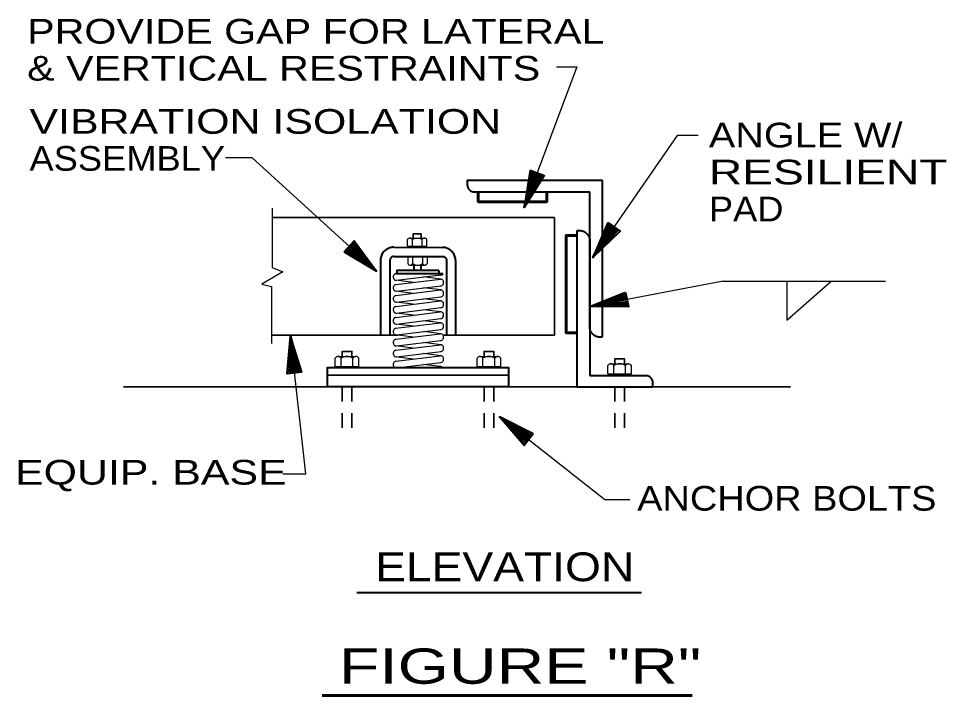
# Model space of a CAD drawing. Extents: x 55 to 190, y 198 to 264.
# Drawn here: x 115.65 to 125.21, y 242.67 to 249.64 of the extents above; entities that cross this region are included whole.
import ezdxf
from ezdxf.enums import TextEntityAlignment as Align

# ---------------------------------------------------------------- set-up
doc = ezdxf.new("R2010")
doc.units = 0
doc.header["$LTSCALE"] = 0.1
doc.linetypes.add('SHORT_DASHED', pattern=[2.7, 1.5, -1.2])
doc.layers.add('2', color=7, linetype='Continuous', lineweight=40)

msp = doc.modelspace()

# ---------------------------------------------------------------- linework, layer by layer
at = {"layer": '2'}
for p, q in [((120.856, 247.6946), (120.9367, 248.0727)), ((120.856, 247.6946), (120.9568, 248.0658)), ((120.856, 247.6946), (120.9727, 248.0592)), ((120.9894, 248.0534), (120.856, 247.6946)), ((120.856, 247.6946), (121.0073, 248.0462)), ((120.856, 247.6946), (121.0423, 248.0333)), ((121.6633, 246.3629), (121.6633, 247.9724)), ((121.532, 246.4542), (121.532, 247.857)), ((121.5632, 247.1826), (121.7344, 247.5292)), ((121.5632, 247.1826), (121.7524, 247.5176)), ((121.4008, 247.4567), (121.4008, 245.8473)), ((121.4474, 247.4567), (121.4008, 247.4567)), ((121.5632, 247.1826), (121.7659, 247.5073)), ((121.7807, 247.4975), (121.5632, 247.1826)), ((121.5632, 247.1826), (121.7963, 247.4864)), ((121.5632, 247.1826), (121.827, 247.4649)), ((119.3362, 247.0397), (119.0912, 247.3387)), ((121.532, 247.3654), (121.532, 245.9626)), ((119.3362, 247.0397), (119.0153, 247.2554)), ((119.3362, 247.0397), (119.0293, 247.2715)), ((119.3362, 247.0397), (119.0412, 247.2837)), ((119.0529, 247.2972), (119.3362, 247.0397)), ((119.3362, 247.0397), (119.0661, 247.3109)), ((119.5151, 247.2866), (120.0146, 247.2855)), ((119.3765, 247.1503), (119.3765, 246.3799)), ((119.4744, 247.1527), (119.4744, 246.3799)), ((119.5167, 247.1927), (120.0149, 247.1927)), ((120.0559, 247.1503), (120.0559, 246.3799)), ((120.1498, 247.1503), (120.1498, 246.3799)), ((119.7194, 247.1035), (119.7194, 247.0466)), ((119.7966, 247.0466), (119.7966, 247.1035)), ((119.9773, 247.0472), (119.9773, 247.0154)), ((119.5352, 247.0154), (120.0207, 247.0154)), ((121.541, 246.6749), (121.9059, 246.8027)), ((121.541, 246.6749), (121.9104, 246.7818)), ((121.541, 246.6749), (121.913, 246.7648)), ((121.9167, 246.7474), (121.541, 246.6749)), ((121.541, 246.6749), (121.9202, 246.7286)), ((121.541, 246.6749), (121.927, 246.6918)), ((118.4499, 246.3719), (118.4369, 245.9856)), ((118.4933, 245.9917), (118.4499, 246.3719)), ((118.4499, 246.3719), (118.5279, 245.9954)), ((118.4499, 246.3719), (118.4742, 245.9899)), ((118.4499, 246.3719), (118.511, 245.9941)), ((118.4499, 246.3719), (118.5491, 245.9983)), ((121.6167, 246.3629), (121.6633, 246.3629)), ((122.1146, 245.9626), (121.532, 245.9626)), ((122.1837, 245.8473), (122.1837, 245.8899)), ((121.4008, 245.8473), (122.1837, 245.8473)), ((120.9042, 245.3041), (120.6036, 245.5409)), ((120.6036, 245.5409), (120.9261, 245.3313)), ((120.6036, 245.5409), (120.869, 245.2599)), ((120.6036, 245.5409), (120.8923, 245.2892)), ((120.6036, 245.5409), (120.915, 245.3184)), ((120.6036, 245.5409), (120.9388, 245.3485)), ((119.1346, 243.7319), (122.0667, 243.7319))]:
    msp.add_line(p, q, dxfattribs=at)
at = {"layer": '2', "lineweight": 25}
for p, q in [((119.6553, 247.2964), (119.6553, 247.3662)), ((119.6805, 247.3813), (119.8308, 247.3813)), ((119.7051, 247.2964), (119.7051, 247.3662)), ((119.8059, 247.2964), (119.8059, 247.3662)), ((119.8559, 247.2964), (119.8559, 247.3657)), ((119.6553, 247.2964), (119.8559, 247.2964)), ((119.6585, 247.1876), (119.8591, 247.1876)), ((119.6585, 247.1876), (119.6585, 247.1178)), ((119.7082, 247.1876), (119.7082, 247.1178)), ((119.809, 247.1876), (119.809, 247.1178)), ((119.8591, 247.1876), (119.8591, 247.1183)), ((119.6836, 247.1027), (119.8339, 247.1027)), ((119.7135, 246.9246), (119.5352, 246.9463)), ((119.5355, 246.9027), (119.9935, 246.959)), ((119.5421, 246.9466), (119.9998, 247.003)), ((120.0001, 246.959), (119.8215, 246.981)), ((119.5352, 246.79), (119.9929, 246.8463)), ((119.5423, 246.8339), (120.0004, 246.8903)), ((120.0006, 246.8463), (119.8218, 246.8683)), ((122.9049, 246.936), (121.541, 246.6749)), ((122.9049, 246.936), (124.5798, 246.936)), ((119.7138, 246.8119), (119.5357, 246.8336)), ((119.5421, 246.7212), (119.9998, 246.7775)), ((120.0001, 246.7336), (119.8215, 246.7556)), ((119.7135, 246.6992), (119.5352, 246.7209)), ((119.5355, 246.6773), (119.9935, 246.7336)), ((119.5423, 246.6085), (120.0004, 246.6648)), ((119.5352, 246.5646), (119.9929, 246.6209)), ((119.7138, 246.5865), (119.5357, 246.6082)), ((120.0006, 246.6209), (119.8218, 246.6429)), ((119.7135, 246.4738), (119.5352, 246.4955)), ((119.5355, 246.4518), (119.9935, 246.5082)), ((119.5421, 246.4958), (119.9998, 246.5521)), ((120.0001, 246.5082), (119.8215, 246.5302)), ((119.5352, 246.3391), (119.9929, 246.3955)), ((119.7138, 246.3611), (119.5357, 246.3828)), ((119.5423, 246.383), (120.0004, 246.4394)), ((120.0006, 246.3955), (119.8218, 246.4174)), ((119.7135, 246.2481), (119.5352, 246.2701)), ((119.5355, 246.2264), (119.9935, 246.2825)), ((119.5421, 246.2703), (119.9998, 246.3264)), ((120.0001, 246.2825), (119.8215, 246.3045)), ((119.5423, 246.1576), (120.0004, 246.2137)), ((120.0006, 246.1698), (119.8218, 246.1917)), ((118.9116, 246.0592), (118.9116, 246.1439)), ((118.942, 246.1624), (119.1241, 246.1624)), ((118.9717, 246.0592), (118.9717, 246.1439)), ((119.0936, 246.0592), (119.0936, 246.1439)), ((119.1542, 246.0592), (119.1542, 246.1433)), ((119.5352, 246.1137), (119.9929, 246.1698)), ((119.7138, 246.1354), (119.5357, 246.1574)), ((119.5421, 246.0449), (119.9998, 246.101)), ((119.9932, 246.0581), (119.8215, 246.079)), ((120.3726, 246.0592), (120.3726, 246.1439)), ((120.403, 246.1624), (120.5851, 246.1624)), ((120.4327, 246.0592), (120.4327, 246.1439)), ((120.5547, 246.0592), (120.5547, 246.1439)), ((120.6152, 246.0592), (120.6152, 246.1433)), ((121.7492, 246.0859), (121.9313, 246.0859)), ((118.9116, 246.0592), (119.1542, 246.0592)), ((119.8853, 246.0449), (119.9932, 246.0581)), ((120.3726, 246.0592), (120.6152, 246.0592)), ((121.7188, 245.9827), (121.7188, 246.0674)), ((121.7188, 245.9827), (121.9614, 245.9827)), ((121.7789, 245.9827), (121.7789, 246.0674)), ((121.9008, 245.9827), (121.9008, 246.0674)), ((121.9614, 245.9827), (121.9614, 246.0669))]:
    msp.add_line(p, q, dxfattribs=at)
at = {"layer": '2', "lineweight": 35}
for p, q in [((119.5566, 246.3799), (118.2557, 246.3799)), ((121.1682, 246.3799), (120.0223, 246.3799)), ((118.8309, 245.97), (120.6951, 245.97)), ((116.7293, 245.8473), (123.5997, 245.8473))]:
    msp.add_line(p, q, dxfattribs=at)
at = {"layer": '2', "linetype": 'SHORT_DASHED', "lineweight": 35}
for p, q in [((118.9833, 245.8475), (118.9833, 245.3401)), ((119.083, 245.8475), (119.083, 245.3401)), ((120.4443, 245.8475), (120.4443, 245.3401)), ((120.5441, 245.8475), (120.5441, 245.3401)), ((121.7905, 245.8475), (121.7905, 245.3401)), ((121.8903, 245.8475), (121.8903, 245.3401))]:
    msp.add_line(p, q, dxfattribs=at)
at = {"layer": '2', "lineweight": 60}
msp.add_line((118.7761, 242.6704), (122.5867, 242.6704), dxfattribs=at)
at = {"layer": '2', "lineweight": 25}
for points in [[(121.1904, 249.1445), (121.3976, 249.1445), (120.856, 247.6946)], [(122.6483, 248.4389), (122.4343, 248.4389), (121.5632, 247.1826)], [(117.78, 248.2105), (118.0512, 248.2105), (119.3362, 247.0397)], [(118.2628, 247.6898), (118.2628, 247.0765), (118.3697, 247.0337), (118.1557, 246.9051), (118.2557, 246.8836), (118.2557, 246.2957)], [(123.5624, 246.9352), (123.5624, 246.5352), (124.0143, 246.9321)], [(118.3702, 244.954), (118.6094, 244.954), (118.4499, 246.3719)], [(121.9456, 244.6842), (121.6887, 244.6842), (120.6036, 245.5409)]]:
    msp.add_lwpolyline(points, dxfattribs=at)
at = {"layer": '2'}
for points in [[(120.9185, 248.0796), (121.0616, 248.0256), (120.856, 247.6946)], [(120.9185, 248.0796), (120.856, 247.6946), (121.0251, 248.0399)], [(121.6633, 247.9724), (120.271, 247.9724), (120.271, 247.9298)], [(120.2716, 247.9351), (120.2713, 247.9303), (120.2713, 247.9253), (120.2718, 247.9205), (120.2726, 247.9155), (120.2737, 247.9108), (120.2753, 247.906), (120.2768, 247.9015), (120.2789, 247.897), (120.2813, 247.8925), (120.284, 247.8885), (120.2869, 247.8846), (120.2901, 247.8806), (120.2935, 247.8771), (120.2972, 247.874), (120.3012, 247.8708), (120.3052, 247.8682), (120.3097, 247.8655), (120.3139, 247.8634), (120.3186, 247.8615), (120.3231, 247.86), (120.3279, 247.8586), (120.3329, 247.8578), (120.3377, 247.857), (120.3401, 247.857), (121.532, 247.857)], [(121.7186, 247.5403), (121.844, 247.4528), (121.5632, 247.1826)], [(121.7186, 247.5403), (121.5632, 247.1826), (121.8122, 247.4758)], [(121.4474, 247.4567), (121.4521, 247.4554), (121.4571, 247.4541), (121.4619, 247.4525), (121.4667, 247.4506), (121.4712, 247.4485), (121.4757, 247.4461), (121.4802, 247.4438), (121.4844, 247.4411), (121.4886, 247.4382), (121.4926, 247.435), (121.4966, 247.4319), (121.5003, 247.4281), (121.5037, 247.4247), (121.5072, 247.421), (121.5103, 247.417), (121.5132, 247.4128), (121.5162, 247.4086), (121.5188, 247.4043), (121.5212, 247.3998), (121.5233, 247.3953), (121.5254, 247.3906), (121.527, 247.3858), (121.5286, 247.381), (121.5299, 247.3763), (121.5323, 247.3654)], [(119.0021, 247.2408), (119.1055, 247.3538), (119.3362, 247.0397)], [(119.0021, 247.2408), (119.3362, 247.0397), (119.0788, 247.3252)], [(119.5151, 247.2866), (119.5045, 247.2863), (119.4937, 247.285), (119.4834, 247.2829), (119.473, 247.28), (119.4606, 247.2763), (119.4508, 247.2718), (119.4416, 247.2665), (119.4326, 247.2607), (119.4241, 247.2541), (119.4164, 247.2466), (119.409, 247.239), (119.4024, 247.2305), (119.3966, 247.2215), (119.3913, 247.2123), (119.3868, 247.2025), (119.3831, 247.1924), (119.3802, 247.1821), (119.3781, 247.1718), (119.3767, 247.1612), (119.3765, 247.1503)], [(120.1498, 247.1503), (120.1493, 247.1609), (120.148, 247.1715), (120.1461, 247.1818), (120.1432, 247.1921), (120.1395, 247.2022), (120.135, 247.2117), (120.13, 247.221), (120.1239, 247.2297), (120.1173, 247.2382), (120.1102, 247.2459), (120.1025, 247.253), (120.094, 247.2596), (120.0853, 247.2654), (120.076, 247.2707), (120.0665, 247.2752), (120.0564, 247.2789), (120.0461, 247.2816), (120.0358, 247.2837), (120.0252, 247.285), (120.0146, 247.2855)], [(119.5167, 247.1927), (119.5132, 247.1924), (119.5101, 247.1921), (119.5066, 247.1916), (119.5035, 247.1906), (119.5003, 247.1895), (119.4974, 247.1879), (119.4945, 247.1863), (119.4918, 247.1845), (119.4892, 247.1826), (119.4865, 247.1802), (119.4844, 247.1779), (119.4823, 247.1752), (119.4804, 247.1723), (119.4789, 247.1694), (119.4775, 247.1665), (119.4762, 247.1633), (119.4754, 247.1601), (119.4749, 247.157), (119.4744, 247.1535), (119.4744, 247.1527)], [(120.0149, 247.1927), (120.0181, 247.1927), (120.0212, 247.1921), (120.0244, 247.1916), (120.0276, 247.1908), (120.0308, 247.1898), (120.0337, 247.1884), (120.0366, 247.1869), (120.0392, 247.185), (120.0419, 247.1831), (120.0443, 247.1808), (120.0464, 247.1784), (120.0485, 247.176), (120.0504, 247.1734), (120.0519, 247.1704), (120.0533, 247.1675), (120.0546, 247.1644), (120.0554, 247.1612), (120.0559, 247.158), (120.0564, 247.1548), (120.0564, 247.1516)], [(119.9773, 247.0472), (119.5447, 247.0472), (119.5447, 247.0154)], [(121.9022, 246.8217), (121.9308, 246.6712), (121.541, 246.6749)], [(121.9022, 246.8217), (121.541, 246.6749), (121.9239, 246.7098)], [(118.5684, 246.0005), (118.4163, 245.9835), (118.4499, 246.3719)], [(118.5684, 246.0005), (118.4499, 246.3719), (118.4555, 245.9875)], [(121.6167, 246.3629), (121.6119, 246.3643), (121.6069, 246.3656), (121.6021, 246.3672), (121.5974, 246.369), (121.5929, 246.3711), (121.5884, 246.3735), (121.5839, 246.3759), (121.5796, 246.3785), (121.5754, 246.3815), (121.5714, 246.3846), (121.5675, 246.3878), (121.5638, 246.3915), (121.5603, 246.3949), (121.5569, 246.3987), (121.5537, 246.4026), (121.5508, 246.4069), (121.5479, 246.4111), (121.5453, 246.4153), (121.5429, 246.4198), (121.5408, 246.4243), (121.5386, 246.4291), (121.5371, 246.4338), (121.5355, 246.4386), (121.5341, 246.4434), (121.5318, 246.4542)], [(122.1832, 245.8846), (122.1834, 245.8893), (122.1834, 245.8944), (122.1829, 245.8991), (122.1821, 245.9042), (122.181, 245.9089), (122.1795, 245.9137), (122.1779, 245.9182), (122.1758, 245.9227), (122.1734, 245.9272), (122.1707, 245.9311), (122.1678, 245.9351), (122.1646, 245.9391), (122.1612, 245.9425), (122.1575, 245.9457), (122.1535, 245.9489), (122.1496, 245.9515), (122.1451, 245.9542), (122.1408, 245.9563), (122.1361, 245.9581), (122.1316, 245.9597), (122.1268, 245.961), (122.1218, 245.9618), (122.117, 245.9626), (122.1146, 245.9626)], [(120.951, 245.3639), (120.856, 245.2438), (120.6036, 245.5409)], [(120.951, 245.3639), (120.6036, 245.5409), (120.8806, 245.2742)]]:
    msp.add_lwpolyline(points, dxfattribs=at)
at = {"layer": '2', "lineweight": 60}
for points in [[(120.3848, 247.8541), (120.3848, 247.7546), (121.0899, 247.7546), (121.0899, 247.8581)], [(121.4008, 247.4088), (121.2897, 247.4088), (121.2897, 246.4037), (121.4008, 246.4037)]]:
    msp.add_lwpolyline(points, dxfattribs=at)
at = {"layer": '2', "lineweight": 35}
for points in [[(121.1682, 246.3799), (121.1682, 247.5927), (118.2628, 247.5927)], [(119.7969, 247.3818), (119.7969, 247.4239), (119.7146, 247.4239), (119.7146, 247.3818)], [(119.083, 246.1629), (119.083, 246.2137), (118.9833, 246.2137), (118.9833, 246.1629)], [(120.5441, 246.1629), (120.5441, 246.2137), (120.4443, 246.2137), (120.4443, 246.1629)], [(121.8903, 246.0864), (121.8903, 246.1372), (121.7905, 246.1372), (121.7905, 246.0864)]]:
    msp.add_lwpolyline(points, dxfattribs=at)
at = {"layer": '2'}
msp.add_lwpolyline([(120.6951, 245.8475), (118.8309, 245.8475), (118.8309, 246.0489), (120.6951, 246.0489)], close=True, dxfattribs=at)
at = {"layer": '2', "lineweight": 25}
for centre, radius, start, end in [((119.6803, 247.3533), 0.028, 27.8877, 152.03419), ((119.7555, 247.2887), 0.0926, 57.00616, 122.94297), ((119.8307, 247.3531), 0.028, 26.78269, 151.8391), ((119.6835, 247.1307), 0.028, 207.96581, 332.1123), ((119.7586, 247.1953), 0.0926, 237.05703, 302.99384), ((119.8338, 247.1309), 0.028, 208.1609, 333.21731), ((118.9418, 246.1282), 0.0339, 27.8877, 152.03419), ((119.0328, 246.0501), 0.1121, 57.00616, 122.94297), ((119.1238, 246.128), 0.0339, 26.78269, 151.8391), ((120.4029, 246.1282), 0.0339, 27.8877, 152.03419), ((120.4938, 246.0501), 0.1121, 57.00616, 122.94297), ((120.5848, 246.128), 0.0339, 26.78269, 151.8391), ((121.7491, 246.0518), 0.0339, 27.8877, 152.03419), ((121.84, 245.9736), 0.1121, 57.00616, 122.94297), ((121.931, 246.0515), 0.0339, 26.78269, 151.8391)]:
    msp.add_arc(centre, radius, start, end, dxfattribs=at)
for centre, major_axis, start_param, end_param in [((119.5386, 246.9809), (0, -0.0346), 3.251722, 6.393315), ((119.9968, 246.9244), (0, 0.0346), 3.251722, 6.393315), ((119.539, 246.8682), (0, -0.0346), 3.251722, 6.393315), ((119.9964, 246.8117), (0, 0.0346), 3.251722, 6.393315), ((119.5386, 246.7554), (0, -0.0346), 3.251722, 6.393315), ((119.539, 246.6427), (0, -0.0346), 3.251722, 6.393315), ((119.9968, 246.699), (0, 0.0346), 3.251722, 6.393315), ((119.5386, 246.53), (0, -0.0346), 3.251722, 6.393315), ((119.9964, 246.5863), (0, 0.0346), 3.251722, 6.393315), ((119.9968, 246.4736), (0, 0.0346), 3.251722, 6.393315), ((119.539, 246.4173), (0, -0.0346), 3.251722, 6.393315), ((119.9964, 246.3609), (0, 0.0346), 3.251722, 6.393315), ((119.5386, 246.3046), (0, -0.0346), 3.251722, 6.393315), ((119.9968, 246.2482), (0, 0.0346), 3.251722, 6.393315), ((119.539, 246.1919), (0, -0.0346), 3.251722, 6.393315), ((119.5386, 246.0792), (0, -0.0346), 3.251722, 6.393315), ((119.9964, 246.1355), (0, 0.0346), 3.251722, 6.393315), ((119.9932, 246.0235), (0, 0.0346), 5.361733, 6.39416)]:
    msp.add_ellipse(centre, major_axis=major_axis, ratio=0.9, start_param=start_param, end_param=end_param, dxfattribs=at)
at = {"layer": '2'}
msp.add_ellipse((119.9964, 247.0372), major_axis=(0, 0.0346), ratio=0.9, start_param=3.251722, end_param=4.030489, dxfattribs=at)

# ---------------------------------------------------------------- texts
for s, width, p in [('PROVIDE GAP FOR LATERAL', 1.25, (115.7377, 249.3842)), ('& VERTICAL RESTRAINTS', 1.25, (115.7377, 249.0032)), ('VIBRATION ISOLATION', 1.3, (115.762, 248.4555)), ('ANGLE W/', 1.2, (122.7594, 248.315)), ('ASSEMBLY', 1.1, (115.762, 248.0745)), ('RESILIENT ', 1.4, (122.7594, 247.934)), ('PAD', 1.1, (122.7594, 247.553)), ('EQUIP. BASE', 1.3, (115.6133, 244.8421)), ('ANCHOR BOLTS', 1.15, (122.021, 244.5738))]:
    msp.add_text(s, height=0.254, dxfattribs=dict(at, width=width)).set_placement(p)
for s, height, width, p in [('ELEVATION', 0.2963, 1.2, (120.6565, 243.8473)), ('FIGURE "R"', 0.3633, 1.4, (120.8152, 242.7908))]:
    msp.add_text(s, height=height, dxfattribs=dict(at, width=width)).set_placement(p, align=Align.CENTER)

doc.saveas('drawing.dxf')
